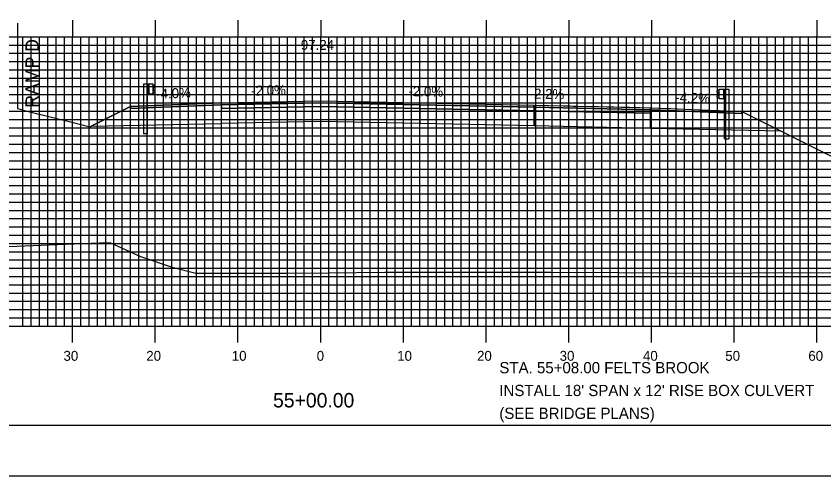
# Model space of a CAD drawing. Extents: x 1756675 to 1757019, y 442591 to 442811.
# Drawn here: x 1756804.3 to 1756901.9, y 442590.5 to 442646.2 of the extents above; entities that cross this region are included whole.
import ezdxf

# ---------------------------------------------------------------- set-up
doc = ezdxf.new("R2010")
doc.units = 0
for name, color, linetype in [('ANNOTATION', 7, 'Continuous'), ('BORDER', 7, 'Continuous'), ('D_Guardrail_Beam_Lt', 7, 'Continuous'), ('D_Guardrail_Beam_Rt', 7, 'Continuous'), ('D_Roadway_Centerline', 7, 'Continuous'), ('D_Roadway_Centerline_Text', 7, 'Continuous'), ('D_Roadway_Edge_Shoulder', 7, 'Continuous'), ('D_Roadway_Edge_TW', 7, 'Continuous'), ('D_Roadway_Pavement', 7, 'Continuous'), ('D_Roadway_SlopeLines', 7, 'Continuous'), ('D_Roadway_SubGrade', 7, 'Continuous'), ('H_V ANNOTATION', 7, 'Continuous'), ('MAJOR', 7, 'Continuous'), ('MINOR', 7, 'Continuous'), ('PLOT BOUNDARY', 7, 'Continuous'), ('S_Roadway_Centerline', 7, 'Continuous')]:
    doc.layers.add(name, color=color, linetype=linetype)

msp = doc.modelspace()

# ---------------------------------------------------------------- linework, layer by layer
at = {"layer": 'BORDER'}
msp.add_lwpolyline([(1756691.483, 442596.665), (1757011.483, 442596.665), (1757011.483, 442806.665), (1756691.483, 442806.665)], close=True, dxfattribs=at)
at = {"layer": 'D_Guardrail_Beam_Lt'}
for p, q in [((1756819.654, 442637.929), (1756819.654, 442631.929)), ((1756820.125, 442637.929), (1756819.654, 442637.929)), ((1756820.812, 442637.929), (1756820.125, 442637.929)), ((1756820.125, 442637.929), (1756820.125, 442636.763)), ((1756820.187, 442637.929), (1756820.187, 442636.763)), ((1756820.291, 442637.929), (1756820.291, 442636.763)), ((1756820.812, 442636.763), (1756820.812, 442637.929)), ((1756820.812, 442637.846), (1756820.886, 442637.831)), ((1756820.902, 442637.825), (1756821.046, 442637.725)), ((1756820.886, 442636.861), (1756820.812, 442636.846)), ((1756820.816, 442637.381), (1756820.816, 442637.311)), ((1756821.046, 442637.582), (1756820.85, 442637.445)), ((1756820.85, 442637.247), (1756821.046, 442637.11)), ((1756821.046, 442636.967), (1756820.902, 442636.867)), ((1756820.125, 442636.763), (1756820.812, 442636.763)), ((1756820.145, 442631.929), (1756820.145, 442636.763)), ((1756820.145, 442631.929), (1756819.654, 442631.929))]:
    msp.add_line(p, q, dxfattribs=at)
for centre, major_axis, start_param, end_param in [((1756820.878, 442637.791), (0.0417, 0), 0.959931, 1.376053), ((1756820.895, 442637.381), (-0.0789, 0), 5.323254, 6.283185), ((1756820.895, 442637.311), (-0.0789, 0), 6.283185, 7.243116), ((1756820.878, 442636.901), (0.0417, 0), 4.907132, 5.323254), ((1756820.995, 442637.653), (0.0877, 0), 5.323254, 7.243116), ((1756820.995, 442637.039), (0.0877, 0), 5.323254, 7.243116)]:
    msp.add_ellipse(centre, major_axis=major_axis, ratio=0.995501, start_param=start_param, end_param=end_param, dxfattribs=at)
at = {"layer": 'D_Guardrail_Beam_Rt'}
for p, q in [((1756889.176, 442637.222), (1756889.032, 442637.122)), ((1756889.032, 442636.979), (1756889.228, 442636.843)), ((1756889.266, 442637.244), (1756889.192, 442637.229)), ((1756889.266, 442637.327), (1756889.953, 442637.327)), ((1756889.266, 442636.16), (1756889.266, 442637.327)), ((1756889.787, 442637.327), (1756889.787, 442636.16)), ((1756889.891, 442637.327), (1756889.891, 442636.16)), ((1756889.953, 442637.327), (1756890.424, 442637.327)), ((1756889.953, 442637.327), (1756889.953, 442636.16)), ((1756890.424, 442637.327), (1756890.424, 442631.327)), ((1756889.228, 442636.644), (1756889.032, 442636.508)), ((1756889.032, 442636.365), (1756889.176, 442636.265)), ((1756889.192, 442636.258), (1756889.266, 442636.244)), ((1756889.261, 442636.779), (1756889.261, 442636.708)), ((1756889.953, 442636.16), (1756889.266, 442636.16)), ((1756889.933, 442631.327), (1756889.933, 442636.16)), ((1756889.933, 442631.327), (1756890.424, 442631.327))]:
    msp.add_line(p, q, dxfattribs=at)
for centre, major_axis, start_param, end_param in [((1756889.083, 442637.051), (-0.0877, 0), 5.323254, 7.243116), ((1756889.2, 442637.188), (-0.0417, 0), 4.907132, 5.323254), ((1756889.182, 442636.779), (0.0789, 0), 0, 0.959931), ((1756889.083, 442636.436), (-0.0877, 0), 5.323254, 7.243116), ((1756889.2, 442636.299), (-0.0417, 0), 0.959931, 1.376053), ((1756889.182, 442636.708), (0.0789, 0), 5.323254, 6.283185)]:
    msp.add_ellipse(centre, major_axis=major_axis, ratio=0.995501, start_param=start_param, end_param=end_param, dxfattribs=at)
at = {"layer": 'D_Roadway_Centerline'}
for points in [[(1756813.191, 442632.78), (1756813.333, 442632.851), (1756818.083, 442635.226), (1756821.083, 442635.346), (1756829.083, 442635.666), (1756841.083, 442635.906), (1756853.083, 442635.666), (1756866.911, 442635.389), (1756870.478, 442635.311), (1756871.257, 442635.294), (1756871.605, 442635.286), (1756874.664, 442635.219), (1756878.429, 442635.136), (1756880.964, 442635.08), (1756883.39, 442634.979), (1756885.909, 442634.873), (1756888.995, 442634.744), (1756889.294, 442634.731), (1756889.946, 442634.704), (1756891.344, 442634.645), (1756892.006, 442634.617), (1756896.302, 442632.469), (1756896.775, 442632.233), (1756901.464, 442629.887), (1756902.834, 442629.202)], [(1756804.428, 442634.97), (1756805.04, 442634.817), (1756805.117, 442634.798), (1756806.235, 442634.518), (1756807.892, 442634.104), (1756808.681, 442633.907), (1756810.356, 442633.489), (1756813.191, 442632.78)]]:
    msp.add_lwpolyline(points, dxfattribs=at)
at = {"layer": 'D_Roadway_Edge_Shoulder'}
for points in [[(1756829.083, 442635.666), (1756821.083, 442635.346), (1756821.083, 442635.346), (1756818.083, 442635.226), (1756818.083, 442634.976), (1756829.083, 442635.416)], [(1756880.964, 442635.08), (1756888.995, 442634.744), (1756888.995, 442634.744), (1756892.006, 442634.617), (1756892.006, 442634.367), (1756880.964, 442634.83)]]:
    msp.add_lwpolyline(points, close=True, dxfattribs=at)
at = {"layer": 'D_Roadway_Edge_TW'}
for points in [[(1756829.083, 442635.416), (1756829.083, 442635.666), (1756841.083, 442635.906), (1756853.083, 442635.666), (1756853.083, 442635.416), (1756841.083, 442635.656)], [(1756853.083, 442635.666), (1756866.911, 442635.389), (1756866.911, 442635.139), (1756853.083, 442635.416)], [(1756866.911, 442635.389), (1756880.964, 442635.08), (1756880.964, 442634.83), (1756866.911, 442635.139)]]:
    msp.add_lwpolyline(points, close=True, dxfattribs=at)
at = {"layer": 'D_Roadway_Pavement'}
for points in [[(1756829.083, 442634.999), (1756829.083, 442635.416), (1756841.083, 442635.656), (1756853.083, 442635.416), (1756853.083, 442634.999), (1756841.083, 442635.239)], [(1756853.083, 442635.416), (1756866.911, 442635.139), (1756866.911, 442634.723), (1756853.083, 442634.999)], [(1756866.911, 442635.139), (1756880.964, 442634.83), (1756880.964, 442634.414), (1756866.911, 442634.723)]]:
    msp.add_lwpolyline(points, close=True, dxfattribs=at)
for points in [[(1756829.083, 442635.416), (1756829.083, 442634.999)], [(1756880.964, 442634.83), (1756880.964, 442634.414)], [(1756880.964, 442634.83), (1756880.964, 442634.414)]]:
    msp.add_lwpolyline(points, dxfattribs=at)
at = {"layer": 'D_Roadway_SlopeLines'}
for points in [[(1756818.083, 442635.226), (1756813.191, 442632.78)], [(1756892.006, 442634.617), (1756930.959, 442615.135)]]:
    msp.add_lwpolyline(points, dxfattribs=at)
at = {"layer": 'D_Roadway_SubGrade'}
msp.add_line((1756804.428, 442645.308), (1756804.428, 442634.97), dxfattribs=at)
for points in [[(1756829.083, 442634.999), (1756829.083, 442635.416), (1756818.083, 442634.976), (1756818.083, 442635.226), (1756813.333, 442632.851), (1756829.083, 442633.166)], [(1756829.083, 442633.166), (1756829.083, 442634.999), (1756841.083, 442635.239), (1756853.083, 442634.999), (1756853.083, 442633.166), (1756841.083, 442633.406)], [(1756853.083, 442634.999), (1756866.911, 442634.723), (1756866.911, 442632.889), (1756853.083, 442633.166)], [(1756866.911, 442634.723), (1756880.964, 442634.414), (1756880.964, 442632.58), (1756866.911, 442632.889)], [(1756880.964, 442634.414), (1756880.964, 442634.83), (1756892.006, 442634.367), (1756892.006, 442634.617), (1756896.775, 442632.233), (1756880.964, 442632.58)]]:
    msp.add_lwpolyline(points, close=True, dxfattribs=at)
at = {"layer": 'MAJOR'}
for p, q in [((1756811.083, 442645.669), (1756811.083, 442643.665)), ((1756821.083, 442645.669), (1756821.083, 442643.665)), ((1756831.083, 442645.669), (1756831.083, 442643.665)), ((1756841.083, 442645.669), (1756841.083, 442643.665)), ((1756851.083, 442645.669), (1756851.083, 442643.665)), ((1756861.083, 442645.669), (1756861.083, 442643.665)), ((1756871.083, 442645.669), (1756871.083, 442643.665)), ((1756881.083, 442645.669), (1756881.083, 442643.665)), ((1756891.083, 442645.669), (1756891.083, 442643.665)), ((1756901.083, 442645.669), (1756901.083, 442643.665)), ((1756701.083, 442643.665), (1756981.083, 442643.665)), ((1756701.083, 442643.665), (1756981.083, 442643.665)), ((1756811.083, 442608.665), (1756811.083, 442643.665)), ((1756821.083, 442608.665), (1756821.083, 442643.665)), ((1756831.083, 442608.665), (1756831.083, 442643.665)), ((1756841.083, 442608.665), (1756841.083, 442643.665)), ((1756851.083, 442608.665), (1756851.083, 442643.665)), ((1756861.083, 442608.665), (1756861.083, 442643.665)), ((1756871.083, 442608.665), (1756871.083, 442643.665)), ((1756881.083, 442608.665), (1756881.083, 442643.665)), ((1756891.083, 442608.665), (1756891.083, 442643.665)), ((1756901.083, 442608.665), (1756901.083, 442643.665)), ((1756701.083, 442638.665), (1756981.083, 442638.665)), ((1756701.083, 442633.665), (1756981.083, 442633.665)), ((1756701.083, 442628.665), (1756981.083, 442628.665)), ((1756701.083, 442623.665), (1756981.083, 442623.665)), ((1756701.083, 442618.665), (1756981.083, 442618.665)), ((1756701.083, 442613.665), (1756981.083, 442613.665)), ((1756701.083, 442608.665), (1756981.083, 442608.665)), ((1756701.083, 442608.665), (1756981.083, 442608.665)), ((1756811.083, 442606.661), (1756811.083, 442608.665)), ((1756821.083, 442606.661), (1756821.083, 442608.665)), ((1756831.083, 442606.661), (1756831.083, 442608.665)), ((1756841.083, 442606.661), (1756841.083, 442608.665)), ((1756851.083, 442606.661), (1756851.083, 442608.665)), ((1756861.083, 442606.661), (1756861.083, 442608.665)), ((1756871.083, 442606.661), (1756871.083, 442608.665)), ((1756881.083, 442606.661), (1756881.083, 442608.665)), ((1756891.083, 442606.661), (1756891.083, 442608.665)), ((1756901.083, 442606.661), (1756901.083, 442608.665))]:
    msp.add_line(p, q, dxfattribs=at)
at = {"layer": 'MINOR'}
for p, q in [((1756805.083, 442608.665), (1756805.083, 442643.665)), ((1756806.083, 442608.665), (1756806.083, 442643.665)), ((1756807.083, 442608.665), (1756807.083, 442643.665)), ((1756808.083, 442608.665), (1756808.083, 442643.665)), ((1756809.083, 442608.665), (1756809.083, 442643.665)), ((1756810.083, 442608.665), (1756810.083, 442643.665)), ((1756812.083, 442608.665), (1756812.083, 442643.665)), ((1756813.083, 442608.665), (1756813.083, 442643.665)), ((1756814.083, 442608.665), (1756814.083, 442643.665)), ((1756815.083, 442608.665), (1756815.083, 442643.665)), ((1756816.083, 442608.665), (1756816.083, 442643.665)), ((1756817.083, 442608.665), (1756817.083, 442643.665)), ((1756818.083, 442608.665), (1756818.083, 442643.665)), ((1756819.083, 442608.665), (1756819.083, 442643.665)), ((1756820.083, 442608.665), (1756820.083, 442643.665)), ((1756822.083, 442608.665), (1756822.083, 442643.665)), ((1756823.083, 442608.665), (1756823.083, 442643.665)), ((1756824.083, 442608.665), (1756824.083, 442643.665)), ((1756825.083, 442608.665), (1756825.083, 442643.665)), ((1756826.083, 442608.665), (1756826.083, 442643.665)), ((1756827.083, 442608.665), (1756827.083, 442643.665)), ((1756828.083, 442608.665), (1756828.083, 442643.665)), ((1756829.083, 442608.665), (1756829.083, 442643.665)), ((1756830.083, 442608.665), (1756830.083, 442643.665)), ((1756832.083, 442608.665), (1756832.083, 442643.665)), ((1756833.083, 442608.665), (1756833.083, 442643.665)), ((1756834.083, 442608.665), (1756834.083, 442643.665)), ((1756835.083, 442608.665), (1756835.083, 442643.665)), ((1756836.083, 442608.665), (1756836.083, 442643.665)), ((1756837.083, 442608.665), (1756837.083, 442643.665)), ((1756838.083, 442608.665), (1756838.083, 442643.665)), ((1756839.083, 442608.665), (1756839.083, 442643.665)), ((1756840.083, 442608.665), (1756840.083, 442643.665)), ((1756842.083, 442608.665), (1756842.083, 442643.665)), ((1756843.083, 442608.665), (1756843.083, 442643.665)), ((1756844.083, 442608.665), (1756844.083, 442643.665)), ((1756845.083, 442608.665), (1756845.083, 442643.665)), ((1756846.083, 442608.665), (1756846.083, 442643.665)), ((1756847.083, 442608.665), (1756847.083, 442643.665)), ((1756848.083, 442608.665), (1756848.083, 442643.665)), ((1756849.083, 442608.665), (1756849.083, 442643.665)), ((1756850.083, 442608.665), (1756850.083, 442643.665)), ((1756852.083, 442608.665), (1756852.083, 442643.665)), ((1756853.083, 442608.665), (1756853.083, 442643.665)), ((1756854.083, 442608.665), (1756854.083, 442643.665)), ((1756855.083, 442608.665), (1756855.083, 442643.665)), ((1756856.083, 442608.665), (1756856.083, 442643.665)), ((1756857.083, 442608.665), (1756857.083, 442643.665)), ((1756858.083, 442608.665), (1756858.083, 442643.665)), ((1756859.083, 442608.665), (1756859.083, 442643.665)), ((1756860.083, 442608.665), (1756860.083, 442643.665)), ((1756862.083, 442608.665), (1756862.083, 442643.665)), ((1756863.083, 442608.665), (1756863.083, 442643.665)), ((1756864.083, 442608.665), (1756864.083, 442643.665)), ((1756865.083, 442608.665), (1756865.083, 442643.665)), ((1756866.083, 442608.665), (1756866.083, 442643.665)), ((1756867.083, 442608.665), (1756867.083, 442643.665)), ((1756868.083, 442608.665), (1756868.083, 442643.665)), ((1756869.083, 442608.665), (1756869.083, 442643.665)), ((1756870.083, 442608.665), (1756870.083, 442643.665)), ((1756872.083, 442608.665), (1756872.083, 442643.665)), ((1756873.083, 442608.665), (1756873.083, 442643.665)), ((1756874.083, 442608.665), (1756874.083, 442643.665)), ((1756875.083, 442608.665), (1756875.083, 442643.665)), ((1756876.083, 442608.665), (1756876.083, 442643.665)), ((1756877.083, 442608.665), (1756877.083, 442643.665)), ((1756878.083, 442608.665), (1756878.083, 442643.665)), ((1756879.083, 442608.665), (1756879.083, 442643.665)), ((1756880.083, 442608.665), (1756880.083, 442643.665)), ((1756882.083, 442608.665), (1756882.083, 442643.665)), ((1756883.083, 442608.665), (1756883.083, 442643.665)), ((1756884.083, 442608.665), (1756884.083, 442643.665)), ((1756885.083, 442608.665), (1756885.083, 442643.665)), ((1756886.083, 442608.665), (1756886.083, 442643.665)), ((1756887.083, 442608.665), (1756887.083, 442643.665)), ((1756888.083, 442608.665), (1756888.083, 442643.665)), ((1756889.083, 442608.665), (1756889.083, 442643.665)), ((1756890.083, 442608.665), (1756890.083, 442643.665)), ((1756892.083, 442608.665), (1756892.083, 442643.665)), ((1756893.083, 442608.665), (1756893.083, 442643.665)), ((1756894.083, 442608.665), (1756894.083, 442643.665)), ((1756895.083, 442608.665), (1756895.083, 442643.665)), ((1756896.083, 442608.665), (1756896.083, 442643.665)), ((1756897.083, 442608.665), (1756897.083, 442643.665)), ((1756898.083, 442608.665), (1756898.083, 442643.665)), ((1756899.083, 442608.665), (1756899.083, 442643.665)), ((1756900.083, 442608.665), (1756900.083, 442643.665)), ((1756701.083, 442642.665), (1756981.083, 442642.665)), ((1756701.083, 442641.665), (1756981.083, 442641.665)), ((1756701.083, 442640.665), (1756981.083, 442640.665)), ((1756701.083, 442639.665), (1756981.083, 442639.665)), ((1756701.083, 442637.665), (1756981.083, 442637.665)), ((1756701.083, 442636.665), (1756981.083, 442636.665)), ((1756701.083, 442635.665), (1756981.083, 442635.665)), ((1756701.083, 442634.665), (1756981.083, 442634.665)), ((1756701.083, 442632.665), (1756981.083, 442632.665)), ((1756701.083, 442631.665), (1756981.083, 442631.665)), ((1756701.083, 442630.665), (1756981.083, 442630.665)), ((1756701.083, 442629.665), (1756981.083, 442629.665)), ((1756701.083, 442627.665), (1756981.083, 442627.665)), ((1756701.083, 442626.665), (1756981.083, 442626.665)), ((1756701.083, 442625.665), (1756981.083, 442625.665)), ((1756701.083, 442624.665), (1756981.083, 442624.665)), ((1756701.083, 442622.665), (1756981.083, 442622.665)), ((1756701.083, 442621.665), (1756981.083, 442621.665)), ((1756701.083, 442620.665), (1756981.083, 442620.665)), ((1756701.083, 442619.665), (1756981.083, 442619.665)), ((1756701.083, 442617.665), (1756981.083, 442617.665)), ((1756701.083, 442616.665), (1756981.083, 442616.665)), ((1756701.083, 442615.665), (1756981.083, 442615.665)), ((1756701.083, 442614.665), (1756981.083, 442614.665)), ((1756701.083, 442612.665), (1756981.083, 442612.665)), ((1756701.083, 442611.665), (1756981.083, 442611.665)), ((1756701.083, 442610.665), (1756981.083, 442610.665)), ((1756701.083, 442609.665), (1756981.083, 442609.665))]:
    msp.add_line(p, q, dxfattribs=at)
at = {"layer": 'PLOT BOUNDARY'}
msp.add_lwpolyline([(1756675.296, 442590.547), (1757015.296, 442590.547), (1757015.296, 442810.547), (1756675.296, 442810.547)], close=True, dxfattribs=at)
at = {"layer": 'S_Roadway_Centerline'}
msp.add_lwpolyline([(1756747.558, 442618.881), (1756758.426, 442618.713), (1756759.883, 442618.725), (1756766.497, 442618.675), (1756771.873, 442618.478), (1756783.584, 442618.319), (1756791.514, 442618.239), (1756796.473, 442618.023), (1756810.215, 442618.576), (1756815.39, 442618.765), (1756815.657, 442618.736), (1756819.286, 442617.091), (1756823.12, 442615.789), (1756826.003, 442615.077), (1756836.887, 442615.059), (1756842.086, 442615.1), (1756848.846, 442615.191), (1756858.613, 442615.185), (1756868.929, 442615.181), (1756877.06, 442615.135), (1756889.057, 442615.073), (1756897.493, 442615.146), (1756901.766, 442615.113), (1756905.484, 442615.162)], dxfattribs=at)

# ---------------------------------------------------------------- texts
at = {"layer": 'ANNOTATION'}
for s, height, rotation, p in [('RAMP D', 1.6, 90, (1756806.981, 442635.069)), ('-2.0%', 1.2, 1.14576, (1756832.689, 442636.539)), ('-4.0%', 1.2, 2.29061, (1756821.215, 442636.153)), ('-2.0%', 1.2, 358.85424, (1756851.683, 442636.494)), ('-2.2%', 1.2, 358.73946, (1756866.342, 442636.202)), ('-4.2%', 1.2, 357.59972, (1756883.946, 442635.757))]:
    msp.add_text(s, height=height, rotation=rotation, dxfattribs=at).set_placement(p)
for s, p in [('STA. 55+08.00 FELTS BROOK', (1756862.687, 442602.956)), ("INSTALL 18' SPAN x 12' RISE BOX CULVERT", (1756862.687, 442600.196)), ('(SEE BRIDGE PLANS)', (1756862.687, 442597.436))]:
    msp.add_text(s, height=1.36, dxfattribs=at).set_placement(p)
at = {"layer": 'D_Roadway_Centerline'}
for s, p in [('C', (1756841.078, 442635.906)), ('L', (1756841.083, 442635.899))]:
    msp.add_text(s, height=0.0146, dxfattribs=at).set_placement(p)
at = {"layer": 'D_Roadway_Centerline_Text'}
msp.add_text('97.24', height=1.2, dxfattribs=at).set_placement((1756838.685, 442642.076))
at = {"layer": 'H_V ANNOTATION'}
for s, height, p in [('30', 1.2, (1756809.98, 442604.465)), ('20', 1.2, (1756819.991, 442604.465)), ('10', 1.2, (1756830.334, 442604.465)), ('0', 1.2, (1756840.601, 442604.465)), ('10', 1.2, (1756850.334, 442604.465)), ('20', 1.2, (1756859.991, 442604.465)), ('30', 1.2, (1756869.98, 442604.465)), ('40', 1.2, (1756880.055, 442604.465)), ('50', 1.2, (1756890.012, 442604.465)), ('60', 1.2, (1756900.055, 442604.465)), ('55+00.00', 1.75, (1756835.324, 442598.821))]:
    msp.add_text(s, height=height, dxfattribs=at).set_placement(p)

doc.saveas('drawing.dxf')
